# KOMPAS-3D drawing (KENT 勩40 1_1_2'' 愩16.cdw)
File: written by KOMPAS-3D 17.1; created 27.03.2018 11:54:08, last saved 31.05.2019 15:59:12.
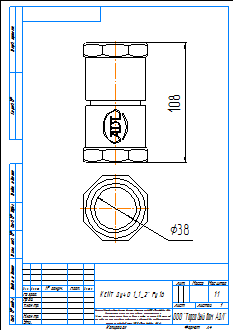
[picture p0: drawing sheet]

Sheet 1: A4, portrait

Title block, sheet 1: name: KENT Ду40 1_1_2'' Ру16; material: Внимание! Данный продукт является объектом авторского права ООО «Торговый Дом АДЛ». / Запрещается изменение, копирование, распространение / (в том числе путем копирования на другие сайты и ресурсы в Интернете) / или любое иное использование информации и объектов без предварительного / согласия правообладателя (ООО «Торговый Дом АДЛ»).; sheets: 1; organisation: ООО "Торговый дом АДЛ"; sheet format: A4; stored path: \\adlc.lan\data\АДЛ_ПКД\3D-модели\Поставщики\Standard Hidraulica\Латунный обратный клапан KENT PN16\KOMPAS 2D\KENT Ду40 1_1_2'' Ру16.cdw

Views: Вид 1, Проекционный вид 2
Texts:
  kka
  adl
Dimensions and other numbers on the sheet: 108; 38; 1:1; 1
